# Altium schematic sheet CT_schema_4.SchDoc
size 258 x 163 mm
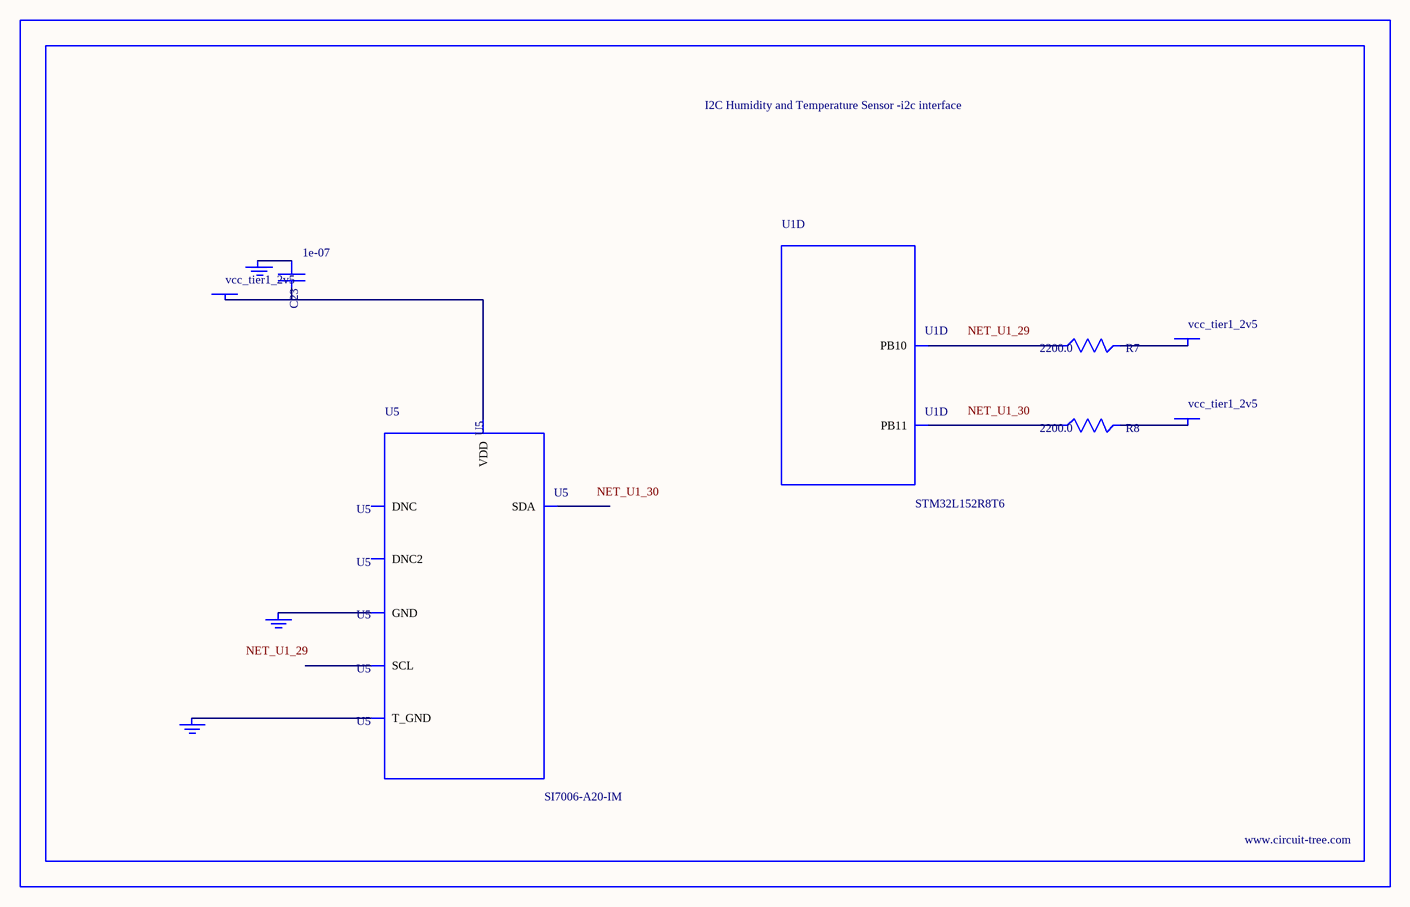
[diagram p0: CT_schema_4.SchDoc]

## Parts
BORDER3  (no value)
C23  1e-07  [C0402]
GND_INSTANCE_3_0  (no value)
GND_INSTANCE_3_1  (no value)
GND_INSTANCE_3_2  (no value)
POWER_INSTANCE_3_0  vcc_tier1_2v5
POWER_INSTANCE_3_1  vcc_tier1_2v5
POWER_INSTANCE_3_2  vcc_tier1_2v5
R7  2200.0  [R0603]
R8  2200.0  [R0603]
U1  STM32L152R8T6  [LQFP64]  (part D of 6)
U5  SI7006-A20-IM  [DFN-6]

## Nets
NetC23_1: C23.1 GND_INSTANCE_3_0.0(GND)
NetC23_2: C23.2 POWER_INSTANCE_3_0.0(PWR) U5.5(VDD)
NetGND_INSTANCE_3_1_0: GND_INSTANCE_3_1.0(GND) U5.7(T_GND)
NetGND_INSTANCE_3_2_0: GND_INSTANCE_3_2.0(GND) U5.2(GND)
NetPOWER_INSTANCE_3_1_0: POWER_INSTANCE_3_1.0(PWR) R7.2
NetPOWER_INSTANCE_3_2_0: POWER_INSTANCE_3_2.0(PWR) R8.2
NetR7_1: R7.1 U1.29(PB10)
NetR8_1: R8.1 U1.30(PB11)

Not connected (* = marked no-connect by the designer): U5 1(SDA) 3(DNC) 4(DNC2) 6(SCL)

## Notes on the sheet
- Labels drawn without touching a wire or pin: NET_U1_29, NET_U1_30

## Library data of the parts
BORDER3 = BORDER_PAGE3
C23 = C0402C104K3RACTU
GND_INSTANCE_3_0-GND_INSTANCE_3_2 = GND
POWER_INSTANCE_3_0-POWER_INSTANCE_3_2 = PWR
R7 R8 = RC0603JR-072K2L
